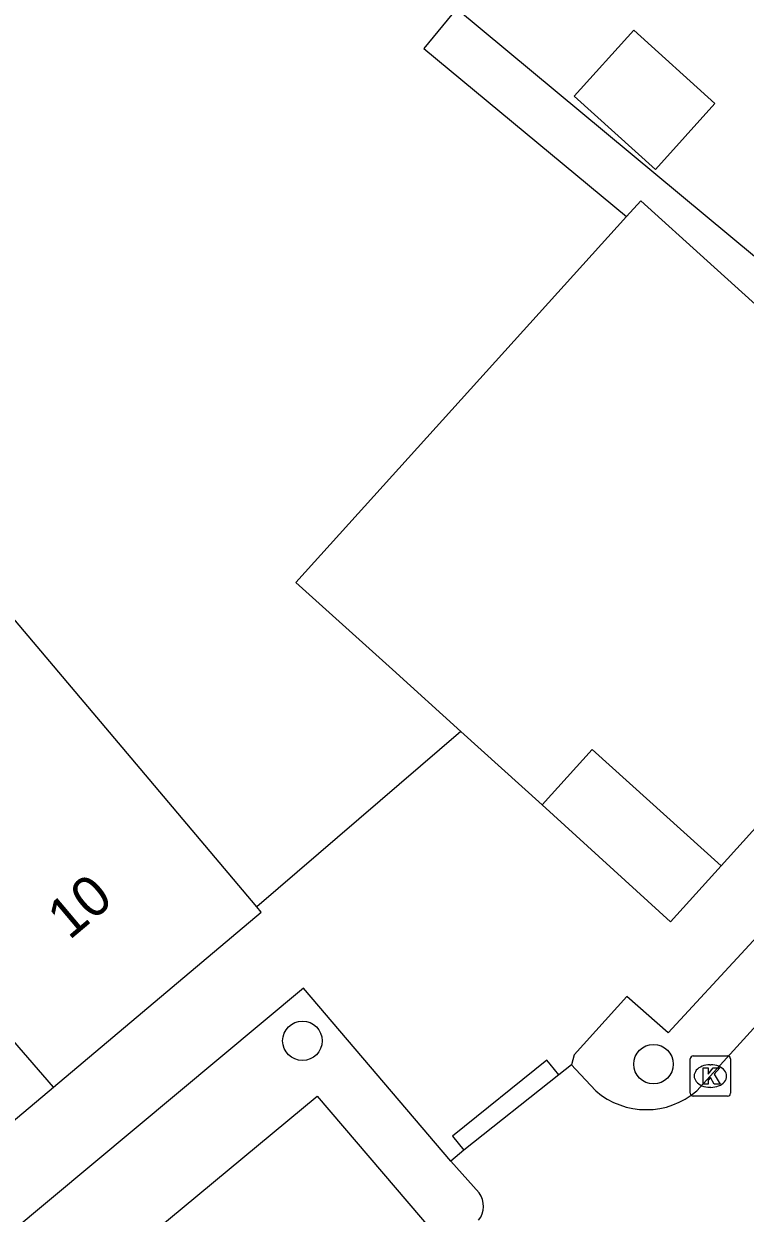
# Model space of a CAD drawing. Extents: x 161882 to 162509, y 381687 to 382379.
# Drawn here: x 162337.67 to 162355.53, y 381900.52 to 381929.98 of the extents above; entities that cross this region are included whole.
import ezdxf

# ---------------------------------------------------------------- set-up
doc = ezdxf.new("R2010")
doc.units = 0
for name, color, linetype in [('IMGEO_Boom', 7, 'Continuous'), ('IMGEO_Kolk', 7, 'Continuous'), ('IMGEO_Pand', 7, 'Continuous'), ('IMGEO_Pand_nummerreeks', 7, 'Continuous'), ('IMGEO_Pand_overbouw', 7, 'Continuous'), ('IMGEO_Parkeervlak_open', 7, 'Continuous'), ('IMGEO_Rijbaan_lokaal_open', 7, 'Continuous'), ('IMGEO_Voetpad_open', 7, 'Continuous')]:
    doc.layers.add(name, color=color, linetype=linetype)

msp = doc.modelspace()

# ---------------------------------------------------------------- linework, layer by layer
at = {"layer": 'IMGEO_Boom'}
for centre in [(162344.569, 381904.793), (162353.264, 381904.214)]:
    msp.add_circle(centre, 0.489, dxfattribs=at)
at = {"layer": 'IMGEO_Kolk'}
for p, q in [((162354.246, 381904.42), (162355.098, 381904.42)), ((162354.171, 381903.494), (162354.171, 381904.346)), ((162354.659, 381904.2), (162354.684, 381904.2)), ((162355.172, 381904.346), (162355.172, 381903.494)), ((162354.682, 381903.64), (162354.657, 381903.64)), ((162355.098, 381903.42), (162354.246, 381903.42))]:
    msp.add_line(p, q, dxfattribs=at)
for points in [[(162354.246, 381904.42), (162355.098, 381904.42)], [(162354.171, 381903.494), (162354.171, 381904.346)], [(162355.172, 381904.346), (162355.172, 381903.494)], [(162354.492, 381904.12), (162354.615, 381904.12), (162354.615, 381903.969), (162354.745, 381904.12), (162354.909, 381904.12), (162354.763, 381903.969), (162354.916, 381903.72), (162354.764, 381903.72), (162354.679, 381903.884), (162354.615, 381903.817), (162354.615, 381903.72), (162354.492, 381903.72), (162354.492, 381904.12)], [(162355.098, 381903.42), (162354.246, 381903.42)]]:
    msp.add_lwpolyline(points, dxfattribs=at)
for centre, start, end in [((162354.248, 381904.344), 91.552, 178.448), ((162354.248, 381904.344), 91.552, 178.448), ((162355.096, 381904.344), 1.552, 88.448), ((162355.096, 381904.344), 1.552, 88.448), ((162354.248, 381903.496), 181.552, 268.448), ((162354.248, 381903.496), 181.552, 268.448), ((162355.096, 381903.496), 271.552, 358.448), ((162355.096, 381903.496), 271.552, 358.448)]:
    msp.add_arc(centre, 0.0765, start, end, dxfattribs=at)
for centre, major_axis, ratio, start_param, end_param in [((162354.658, 381903.92), (-0.387, 0.002), 0.722429, 4.712389, 7.853982), ((162354.683, 381903.92), (-0.39, 0.002), 0.717154, 1.570796, 4.712389)]:
    msp.add_ellipse(centre, major_axis=major_axis, ratio=ratio, start_param=start_param, end_param=end_param, dxfattribs=at)
at = {"layer": 'IMGEO_Pand'}
for points in [[(162351.302, 381928.19), (162353.31, 381926.376), (162354.786, 381928.011), (162352.779, 381929.825), (162351.302, 381928.19)], [(162352.593, 381925.207), (162352.947, 381925.599), (162354.594, 381924.111), (162358.529, 381920.557), (162362.239, 381917.205)], [(162352.593, 381925.207), (162344.408, 381916.147), (162346.798, 381913.989), (162348.493, 381912.458)], [(162343.439, 381908.114), (162340.325, 381911.802), (162332.799, 381920.714), (162332.702, 381920.828), (162336.276, 381923.854), (162334.722, 381924.911)], [(162361.239, 381916.098), (162354.94, 381909.125)], [(162350.508, 381910.637), (162348.493, 381912.458)], [(162354.94, 381909.125), (162351.747, 381912.009), (162350.508, 381910.637)], [(162338.405, 381903.648), (162331.614, 381911.491), (162324.457, 381905.392)], [(162338.405, 381903.648), (162343.551, 381907.982), (162343.439, 381908.114)], [(162331.126, 381897.517), (162338.405, 381903.648)]]:
    msp.add_lwpolyline(points, dxfattribs=at)
at = {"layer": 'IMGEO_Pand_overbouw'}
msp.add_lwpolyline([(162351.747, 381912.009), (162350.508, 381910.637), (162353.682, 381907.742), (162354.94, 381909.125)], close=True, dxfattribs=at)
at = {"layer": 'IMGEO_Parkeervlak_open'}
msp.add_lwpolyline([(162326.524, 381883.594), (162324.21, 381886.239), (162333.494, 381893.939), (162344.935, 381903.424), (162347.83, 381900.027)], dxfattribs=at)
at = {"layer": 'IMGEO_Rijbaan_lokaal_open'}
for points in [[(162358.189, 381907.794), (162357.389, 381906.913), (162354.336, 381903.551)], [(162351.235, 381904.201), (162350.917, 381903.949)], [(162351.834, 381903.55), (162351.334, 381904.087), (162351.235, 381904.201)], [(162350.917, 381903.949), (162348.565, 381902.085)], [(162348.565, 381902.085), (162348.241, 381901.811)], [(162348.945, 381901.024), (162348.241, 381901.811)]]:
    msp.add_lwpolyline(points, dxfattribs=at)
for centre, radius, start, end in [((162353.084, 381905.011), 1.923, 229.4438, 310.602), ((162348.51, 381900.695), 0.545, 320.5007, 37.1265)]:
    msp.add_arc(centre, radius, start, end, dxfattribs=at)
at = {"layer": 'IMGEO_Voetpad_open'}
for points in [[(162356.398, 381923.694), (162348.389, 381930.351), (162347.578, 381929.375), (162352.593, 381925.207)], [(162348.493, 381912.458), (162343.439, 381908.114)], [(162350.508, 381910.637), (162353.682, 381907.742), (162354.94, 381909.125)], [(162357.444, 381909.116), (162353.626, 381904.992), (162352.601, 381905.888), (162351.3, 381904.448), (162351.235, 381904.201)], [(162348.241, 381901.811), (162344.595, 381906.095), (162320.529, 381886.009)], [(162350.917, 381903.949), (162350.701, 381904.214), (162350.624, 381904.311), (162348.285, 381902.431), (162348.565, 381902.085)]]:
    msp.add_lwpolyline(points, dxfattribs=at)

# ---------------------------------------------------------------- texts
at = {"layer": 'IMGEO_Pand_nummerreeks'}
msp.add_text('10', height=1, rotation=40.107, dxfattribs=at).set_placement((162338.795, 381907.271))

doc.saveas('drawing.dxf')
